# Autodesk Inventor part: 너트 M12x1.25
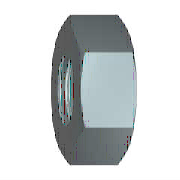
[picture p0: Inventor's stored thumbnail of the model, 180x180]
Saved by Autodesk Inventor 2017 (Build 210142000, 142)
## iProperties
IsCustomPart: 1
Created: 2012-02
Part Number: 너트 M12x1.25
Material: 강철, 연강
Description: 6각 너트
Document SubType Name: Modeling
Standard: KS B 1012
Designer: mduedu
Standards Organization: KS
Language: ko-KR
Size Designation: M12x1.25
Categories: <MemberInstance><Categories><Category DisplayName="조임쇠" InternalName="e4da775c-781d-43d5-af7c-5136215cf5a6" Mnemonic="FSTN"><Category DisplayName="너트" InternalN
Density: 1 g/cm^3
Appearance: 강철
Author: mduedu
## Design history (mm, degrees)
sketch "스케치1"
  geometry: L1 (-10.97, 0)-(-5.485, 9.5); L2 (-5.485, 9.5)-(5.485, 9.5); L3 (5.485, 9.5)-(10.97, 0); L4 (10.97, 0)-(5.485, -9.5); L5 (5.485, -9.5)-(-5.485, -9.5); L6 (-5.485, -9.5)-(-10.97, 0); 2 further points
  constraints: 12 end point, 1 coincident, 1 horizontal, 11 other
  dimensions: "d0" = 21.93931 distance of L3.end L1.start (= 1.1547 x SW)
extrude "본체" new body sketch "스케치1" distance "d1" = 10 (= KOH); taper "d2" = 0 deg
sketch "스케치2"
  geometry: L1 (0, 5.485)-(0, 10.97) reference; L2 (0, 10.97)-(10, 10.97) reference; L3 (10, 5.485)-(10, 10.97) reference; L4 (-2, 0)-(12, 0) reference; L5 (0.849, 10.97)-(0, 9.5); L6 (9.151, 10.97)-(10, 9.5)
  constraints: 4 end point, 4 point on line
  dimensions: "d3" = 30 deg angle of L1 L5 (= ANG1); "d4" = 30 deg angle of L3 L6 (= ANG2); "d5" = 19 diameter of L5.end L4 (= SW0); "d6" = 19 diameter of L6.end L4 (= SW01)
revolve "모따기1" sketch "스케치2" stored, may be unused: angle "d7" = 90 deg
sketch "스케치3"
  geometry: A1 r 9.5 centre (0, 0) between (-4.75, -8.227) and (4.75, -8.227) reference; 1 further point
  constraints: 1 coincident
hole "스레드" sketch "스케치3" at (0, 0) diameter "d25" = 10.647; stored, may be unused: countersink angle "d29" = 82 deg, drill point angle "d31" = 118 deg; dims "d26" = 6, "d27" = 4, "d28" = 2, "d30" = 8
workaxis "Work Axis1"
workplane "Work Plane1"
body "Solid1"
chamfer "모따기2" distance "d8" = 0.67658 (= -0.5 x GD1 + 0.5 x NND); stored, may be unused: angle "d9" = 30 deg, second distance "d40" = 0.67658 (= -0.5 x GD1 + 0.5 x NND)
chamfer "모따기3" distance "d10" = 0.67658 (= -0.5 x GD1 + 0.5 x NND); stored, may be unused: angle "d11" = 30 deg, second distance "d41" = 0.67658 (= -0.5 x GD1 + 0.5 x NND)
other parameters: "ANG1" = 30 deg [user parameter; used in 1 equation term], "ANG2" = 30 deg [user parameter; used in 1 equation term], "NND" = 12 [user parameter; used in 4 equation terms], "KOH" = 10 [user parameter; used in 1 equation term], "SW" = 19 [user parameter; used in 4 equation terms], "SW0" = 19 (= SW) [user parameter; used in 1 equation term], "SW01" = 19 (= SW) [user parameter; used in 1 equation term], "GD1" = 10.64684 (computed from THREADDIA, PTC, TOA) [user parameter; used in 4 equation terms], "d13" = 0, "d14" = 0, "d39" = 0, "d42" = 0, "GUL" = 0.67658 (= 0.541266 x PTC) [user parameter], "TPU" = 8 (computed from PTC) [user parameter], "THREADDIA" = 12 [user parameter; used in 1 equation term], "TOA" = 30 deg [user parameter; used in 1 equation term], "PTC" = 1.25 [user parameter; used in 4 equation terms], "E0" = 21.945 (= 1.155 x SW) [user parameter], "GAL" = 0.67658 (= 0.541266 x PTC) [user parameter]
